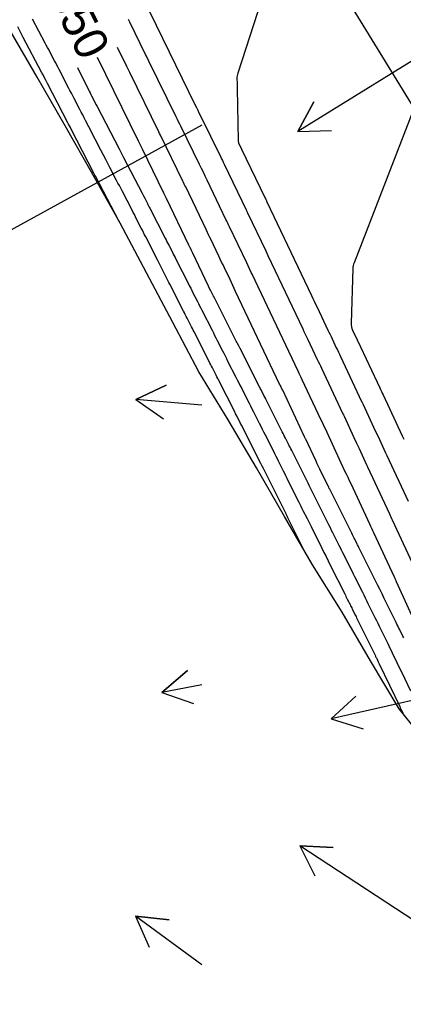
# Model space of a CAD drawing. Extents: x 954385 to 988206, y 1868364 to 1924553.
# Drawn here: x 956974.6 to 957043.1, y 1920910.1 to 1921087.7 of the extents above; entities that cross this region are included whole.
import ezdxf

# ---------------------------------------------------------------- set-up
doc = ezdxf.new("R2010")
doc.units = 0
for name, color, linetype in [('Default', 7, 'Continuous'), ('Ex_Contour Labels', 7, 'Continuous'), ('Ex_Major Contours', 7, 'Continuous'), ('Ex_Minor Contours', 7, 'Continuous'), ('Perimeter', 7, 'Continuous'), ('Slopes', 7, 'Continuous')]:
    doc.layers.add(name, color=color, linetype=linetype)

msp = doc.modelspace()

# ---------------------------------------------------------------- linework, layer by layer
at = {"layer": 'Default'}
msp.add_line((957221.14, 1920784.24), (956045.8, 1922705.18), dxfattribs=at)
at = {"layer": 'Ex_Major Contours'}
for points in [[(957044.52, 1920967.81), (957042.89, 1920971.21), (957042.69, 1920971.64), (957042.48, 1920972.06), (957042.28, 1920972.48), (957042.07, 1920972.91), (957041.26, 1920974.6), (957041.06, 1920975.03), (957040.85, 1920975.45), (957040.64, 1920975.87), (957040.44, 1920976.3), (957038.9, 1920979.4), (957038.66, 1920979.91), (957038.41, 1920980.41), (957038.16, 1920980.92), (957037.91, 1920981.42), (957036.91, 1920983.45), (957036.66, 1920983.95), (957036.41, 1920984.46), (957036.16, 1920984.96), (957035.91, 1920985.47), (957034.52, 1920988.22), (957034.26, 1920988.75), (957034, 1920989.27), (957033.74, 1920989.79), (957033.48, 1920990.31), (957032.36, 1920992.54), (957032.14, 1920992.99), (957031.92, 1920993.43), (957031.7, 1920993.87), (957031.47, 1920994.32), (957030.58, 1920996.09), (957030.36, 1920996.54), (957030.14, 1920996.98), (957029.92, 1920997.43), (957029.69, 1920997.87), (957027.79, 1921001.68), (957027.6, 1921002.04), (957027.42, 1921002.4), (957027.24, 1921002.77), (957027.06, 1921003.13), (957026.33, 1921004.58), (957026.15, 1921004.95), (957025.97, 1921005.31), (957025.78, 1921005.67), (957025.6, 1921006.04), (957023.21, 1921010.82), (957023.07, 1921011.1), (957022.93, 1921011.38), (957022.79, 1921011.65), (957022.65, 1921011.93), (957022.09, 1921013.04), (957021.95, 1921013.31), (957021.81, 1921013.59), (957021.67, 1921013.87), (957021.53, 1921014.14), (957018.6, 1921019.96), (957018.5, 1921020.15), (957018.41, 1921020.33), (957018.31, 1921020.52), (957018.22, 1921020.71), (957017.83, 1921021.46), (957017.74, 1921021.65), (957017.64, 1921021.84), (957017.55, 1921022.02), (957017.45, 1921022.21), (957013.97, 1921029.06), (957013.86, 1921029.27), (957013.75, 1921029.49), (957013.53, 1921029.92), (957013.42, 1921030.14), (957013.31, 1921030.35), (957009.33, 1921038.18), (957009.22, 1921038.39), (957008.69, 1921039.43), (957008.6, 1921039.61), (957008.51, 1921039.79), (957008.42, 1921039.97), (957008.34, 1921040.15), (957005.46, 1921046.18), (957005.31, 1921046.51), (957005.05, 1921047.05), (957005, 1921047.16), (957004.94, 1921047.27), (957004.89, 1921047.38), (957004.84, 1921047.48), (957000.82, 1921055.85), (957000.7, 1921056.09), (957000.59, 1921056.32), (957000.47, 1921056.56), (957000.36, 1921056.79), (956996.52, 1921064.63), (956996.34, 1921064.99), (956996.17, 1921065.34), (956995.99, 1921065.7), (956995.82, 1921066.05), (956988.48, 1921081.03)], [(957044.97, 1921071.73), (957034.36, 1921044.36), (957034.27, 1921044.1), (957034.21, 1921043.84), (957034.16, 1921043.57), (957034.14, 1921043.3), (957033.85, 1921033.57), (957033.85, 1921033.24), (957033.9, 1921032.92), (957033.99, 1921032.6), (957034.11, 1921032.29), (957034.92, 1921030.6), (957034.95, 1921030.54), (957034.98, 1921030.47), (957035.01, 1921030.41), (957035.04, 1921030.35), (957038.97, 1921022.02), (957039.12, 1921021.7), (957039.27, 1921021.38), (957039.42, 1921021.06), (957039.57, 1921020.74), (957042.97, 1921013.43), (957043.25, 1921012.84)]]:
    msp.add_lwpolyline(points, dxfattribs=at)
at = {"layer": 'Ex_Minor Contours'}
for points in [[(957022.06, 1921104.33), (957013.56, 1921078.19), (957013.5, 1921077.97), (957013.45, 1921077.75), (957013.43, 1921077.52), (957013.42, 1921077.29), (957013.44, 1921076.38), (957013.45, 1921076.15), (957013.45, 1921075.92), (957013.46, 1921075.69), (957013.46, 1921075.46), (957013.65, 1921066.16), (957013.66, 1921066.02), (957013.68, 1921065.88), (957013.72, 1921065.74), (957013.78, 1921065.61), (957014.22, 1921064.72), (957014.24, 1921064.68), (957014.26, 1921064.64), (957018.42, 1921055.98), (957018.5, 1921055.8), (957018.59, 1921055.62), (957018.68, 1921055.43), (957018.77, 1921055.25), (957026.75, 1921038.5), (957027, 1921037.98), (957027.24, 1921037.46), (957027.49, 1921036.94), (957027.74, 1921036.42), (957029.69, 1921032.33), (957029.88, 1921031.93), (957030.07, 1921031.54), (957030.25, 1921031.15), (957030.44, 1921030.75), (957031.19, 1921029.18), (957031.38, 1921028.78), (957031.57, 1921028.39), (957031.75, 1921027.99), (957031.94, 1921027.6), (957035.72, 1921019.58), (957035.79, 1921019.44), (957035.86, 1921019.29), (957035.93, 1921019.14), (957036, 1921019), (957037.86, 1921015), (957038.22, 1921014.21), (957038.59, 1921013.43), (957040, 1921010.39), (957040.06, 1921010.28), (957040.11, 1921010.17), (957040.16, 1921010.06), (957040.21, 1921009.94), (957044.02, 1921001.77)], [(957025.46, 1920992.97), (957022.54, 1920998.8), (957022.45, 1920998.99), (957022.28, 1920999.32), (957022.26, 1920999.37), (957018.38, 1921007.12), (957018.32, 1921007.23), (957018.26, 1921007.34), (957018.21, 1921007.46), (957018.15, 1921007.57), (957017.92, 1921008.02), (957017.87, 1921008.13), (957017.81, 1921008.25), (957017.75, 1921008.36), (957017.7, 1921008.47), (957014.23, 1921015.34), (957014.14, 1921015.53), (957014.04, 1921015.71), (957013.95, 1921015.9), (957013.85, 1921016.08), (957013.48, 1921016.83), (957013.38, 1921017.02), (957013.29, 1921017.2), (957013.19, 1921017.39), (957013.1, 1921017.58), (957010.12, 1921023.43), (957009.98, 1921023.7), (957009.84, 1921023.97), (957009.71, 1921024.24), (957009.57, 1921024.51), (957009.02, 1921025.6), (957008.88, 1921025.87), (957008.74, 1921026.14), (957008.6, 1921026.41), (957008.46, 1921026.69), (957005.77, 1921031.99), (957005.61, 1921032.3), (957005.45, 1921032.61), (957005.29, 1921032.92), (957005.14, 1921033.23), (957004.51, 1921034.47), (957004.35, 1921034.77), (957004.19, 1921035.08), (957004.03, 1921035.39), (957003.88, 1921035.7), (957001.43, 1921040.5), (957001.26, 1921040.85), (957001.08, 1921041.2), (957000.9, 1921041.56), (957000.72, 1921041.91), (957000, 1921043.32), (956999.82, 1921043.67), (956999.64, 1921044.02), (956999.46, 1921044.37), (956999.28, 1921044.73), (956997.12, 1921048.95), (956996.91, 1921049.35), (956996.71, 1921049.75), (956996.5, 1921050.15), (956996.3, 1921050.55), (956995.48, 1921052.15), (956995.28, 1921052.55), (956995.07, 1921052.95), (956994.86, 1921053.35), (956994.66, 1921053.75), (956992.87, 1921057.19), (956992.63, 1921057.65), (956992.39, 1921058.12), (956992.14, 1921058.58), (956991.9, 1921059.05), (956990.69, 1921061.38), (956989.97, 1921062.78), (956988.63, 1921065.34), (956988.35, 1921065.88), (956988.07, 1921066.42), (956987.79, 1921066.96), (956987.51, 1921067.5), (956986.33, 1921069.77), (956986.08, 1921070.26), (956985.83, 1921070.74), (956985.58, 1921071.23), (956985.32, 1921071.71), (956984.32, 1921073.66), (956984.06, 1921074.14), (956983.81, 1921074.63), (956983.56, 1921075.12), (956983.31, 1921075.6), (956981.62, 1921078.84), (956981.42, 1921079.24), (956981.21, 1921079.64), (956981, 1921080.03), (956980.79, 1921080.43), (956979.96, 1921082.01), (956979.75, 1921082.41), (956979.54, 1921082.8), (956979.33, 1921083.2), (956979.12, 1921083.59), (956976.85, 1921087.88)], [(957045.96, 1920978.61), (957041.98, 1920987.34), (957041.89, 1920987.54), (957041.79, 1920987.75), (957041.7, 1920987.95), (957041.6, 1920988.16), (957037.91, 1920996.09), (957037.72, 1920996.48), (957037.54, 1920996.87), (957037.36, 1920997.26), (957037.17, 1920997.66), (957033.83, 1921004.83), (957033.56, 1921005.41), (957033.29, 1921005.99), (957033.01, 1921006.57), (957032.74, 1921007.15), (957029.56, 1921014), (957029.3, 1921014.55), (957029.03, 1921015.11), (957028.77, 1921015.67), (957028.51, 1921016.23), (957025.1, 1921023.46), (957024.92, 1921023.84), (957024.74, 1921024.21), (957024.57, 1921024.59), (957024.39, 1921024.96), (957016.12, 1921042.32), (957015.98, 1921042.6), (957015.42, 1921043.78), (957015.17, 1921044.31), (957012.08, 1921050.79), (957011.93, 1921051.11), (957011.77, 1921051.44), (957011.61, 1921051.77), (957011.45, 1921052.1), (957008.08, 1921059.12), (957007.75, 1921059.81), (957007.41, 1921060.5), (957007.07, 1921061.19), (957006.74, 1921061.88), (957003.42, 1921068.64), (957003.21, 1921069.08), (957002.99, 1921069.52), (957002.78, 1921069.96), (957002.56, 1921070.39), (956997.68, 1921080.36), (956997.23, 1921081.27), (956997.08, 1921081.57), (956994.26, 1921087.33), (956994.2, 1921087.44), (956994.15, 1921087.56), (956994.09, 1921087.67), (956994.04, 1921087.78)], [(956997.77, 1921089.21), (957005.96, 1921072.52), (957006.18, 1921072.06), (957006.4, 1921071.61), (957006.63, 1921071.15), (957006.85, 1921070.69), (957010.53, 1921063.19), (957010.68, 1921062.89), (957010.82, 1921062.59), (957010.97, 1921062.29), (957011.12, 1921061.98), (957015.05, 1921053.81), (957015.11, 1921053.67), (957015.18, 1921053.53), (957015.25, 1921053.39), (957015.31, 1921053.25), (957018.56, 1921046.45), (957018.94, 1921045.65), (957025.18, 1921032.54), (957025.41, 1921032.06), (957025.64, 1921031.59), (957025.86, 1921031.11), (957026.09, 1921030.64), (957027.79, 1921027.07), (957027.97, 1921026.68), (957028.16, 1921026.3), (957028.34, 1921025.92), (957028.52, 1921025.53), (957032.32, 1921017.48), (957032.38, 1921017.34), (957032.45, 1921017.2), (957032.51, 1921017.06), (957032.58, 1921016.92), (957034.35, 1921013.11), (957034.81, 1921012.13), (957035.27, 1921011.14), (957036.62, 1921008.25), (957036.66, 1921008.16), (957036.7, 1921008.08), (957036.74, 1921008), (957036.78, 1921007.91), (957040.7, 1920999.5), (957040.82, 1920999.23), (957040.95, 1920998.96), (957041.08, 1920998.69), (957041.2, 1920998.42), (957044.77, 1920990.77)], [(956992.34, 1921051.71), (956988.12, 1921059.84), (956988.03, 1921060.02), (956987.85, 1921060.37), (956983.78, 1921068.19), (956983.63, 1921068.48), (956983.32, 1921069.08), (956983.17, 1921069.37), (956979.53, 1921076.39), (956979.35, 1921076.72), (956979.18, 1921077.06), (956978.83, 1921077.74), (956978.74, 1921077.9), (956978.65, 1921078.07), (956978.56, 1921078.24), (956978.47, 1921078.41), (956975.21, 1921084.58), (956974.96, 1921085.05), (956974.71, 1921085.52), (956974.22, 1921086.46)], [(957043.26, 1920977.33), (957043.11, 1920977.64), (957042.5, 1920978.87), (957042.34, 1920979.18), (957042.19, 1920979.49), (957042.04, 1920979.8), (957041.89, 1920980.11), (957039.78, 1920984.39), (957039.37, 1920985.21), (957038.97, 1920986.02), (957038.56, 1920986.84), (957038.16, 1920987.65), (957035.23, 1920993.49), (957035.16, 1920993.64), (957035.08, 1920993.79), (957035.01, 1920993.94), (957034.93, 1920994.09), (957034.61, 1920994.74), (957034.54, 1920994.87), (957034.48, 1920995), (957034.41, 1920995.13), (957034.35, 1920995.25), (957034.09, 1920995.77), (957033.96, 1920996.03), (957033.83, 1920996.29), (957030.02, 1921003.89), (957029.94, 1921004.05), (957029.84, 1921004.25), (957029.78, 1921004.38), (957028.45, 1921007.04), (957028.22, 1921007.5), (957027.99, 1921007.95), (957027.77, 1921008.42), (957027.56, 1921008.88), (957025.72, 1921012.82), (957025.67, 1921012.92), (957025.62, 1921013.03), (957025.57, 1921013.13), (957025.53, 1921013.23), (957021.6, 1921021.56), (957021.46, 1921021.84), (957021.33, 1921022.12), (957021.2, 1921022.41), (957021.06, 1921022.69), (957013.18, 1921039.23), (957012.93, 1921039.75), (957012.68, 1921040.28), (957012.43, 1921040.8), (957012.18, 1921041.33), (957011.18, 1921043.43), (957010.93, 1921043.95), (957010.68, 1921044.48), (957010.43, 1921045), (957010.18, 1921045.52), (957008.73, 1921048.57), (957008.54, 1921048.96), (957008.36, 1921049.35), (957008.17, 1921049.75), (957007.98, 1921050.14), (957004.26, 1921057.88), (957004.13, 1921058.14), (957004, 1921058.41), (957003.87, 1921058.68), (957003.74, 1921058.95), (956999.73, 1921067.13), (956999.58, 1921067.43), (956999.43, 1921067.73), (956994.24, 1921078.34), (956993.84, 1921079.15), (956993.7, 1921079.42), (956992.04, 1921082.81)], [(956984.92, 1921079.24), (956986.88, 1921075.25), (956987.01, 1921074.98), (956987.15, 1921074.7), (956987.29, 1921074.43), (956987.43, 1921074.16), (956988.25, 1921072.57), (956988.42, 1921072.25), (956992.33, 1921064.72), (956992.46, 1921064.46), (956992.6, 1921064.2), (956993.15, 1921063.15), (956996.47, 1921056.76), (956996.7, 1921056.31), (956996.93, 1921055.86), (956997.4, 1921054.96), (956997.51, 1921054.74), (956997.63, 1921054.51), (956997.75, 1921054.29), (956997.86, 1921054.07), (957000.59, 1921048.74), (957000.75, 1921048.42), (957000.91, 1921048.11), (957001.07, 1921047.79), (957001.23, 1921047.48), (957001.88, 1921046.22), (957002.04, 1921045.9), (957002.2, 1921045.59), (957002.36, 1921045.27), (957002.52, 1921044.96), (957004.76, 1921040.56), (957004.96, 1921040.17), (957005.16, 1921039.78), (957005.36, 1921039.39), (957005.56, 1921039), (957006.35, 1921037.43), (957006.55, 1921037.04), (957006.75, 1921036.65), (957006.95, 1921036.26), (957007.15, 1921035.87), (957008.97, 1921032.29), (957009.2, 1921031.83), (957009.43, 1921031.37), (957009.67, 1921030.92), (957009.9, 1921030.46), (957010.83, 1921028.63), (957011.07, 1921028.17), (957011.3, 1921027.71), (957011.53, 1921027.25), (957011.76, 1921026.79), (957013.22, 1921023.94), (957013.48, 1921023.42), (957013.74, 1921022.9), (957014.01, 1921022.39), (957014.27, 1921021.87), (957015.32, 1921019.8), (957015.59, 1921019.28), (957015.85, 1921018.77), (957016.11, 1921018.25), (957016.37, 1921017.74), (957017.41, 1921015.68), (957017.67, 1921015.17), (957017.93, 1921014.65), (957018.19, 1921014.14), (957018.45, 1921013.62), (957019.93, 1921010.68), (957020.15, 1921010.25), (957020.37, 1921009.81), (957020.59, 1921009.38), (957020.81, 1921008.94), (957021.68, 1921007.2), (957021.9, 1921006.76), (957022.11, 1921006.33), (957022.33, 1921005.89), (957022.55, 1921005.46), (957024.5, 1921001.56), (957024.68, 1921001.2), (957024.86, 1921000.84), (957025.05, 1921000.48), (957025.23, 1921000.11), (957025.95, 1920998.66), (957026.14, 1920998.3), (957026.32, 1920997.94), (957026.5, 1920997.58), (957026.68, 1920997.21), (957028.6, 1920993.38), (957028.98, 1920992.62), (957029.36, 1920991.87), (957029.74, 1920991.11), (957030.12, 1920990.35), (957032.69, 1920985.21), (957032.81, 1920984.98), (957032.92, 1920984.74), (957033.04, 1920984.51), (957033.16, 1920984.28), (957033.66, 1920983.28), (957033.75, 1920983.09), (957033.85, 1920982.89), (957033.95, 1920982.7), (957034.04, 1920982.5), (957034.43, 1920981.72), (957034.52, 1920981.53), (957034.62, 1920981.33), (957034.72, 1920981.14), (957034.81, 1920980.94), (957038.18, 1920974.13), (957038.23, 1920974.01), (957038.29, 1920973.89), (957038.35, 1920973.77), (957038.41, 1920973.64), (957038.7, 1920973.04), (957038.87, 1920972.68), (957042.53, 1920965.07), (957042.64, 1920964.82), (957042.76, 1920964.58), (957043.12, 1920963.83)]]:
    msp.add_lwpolyline(points, dxfattribs=at)
at = {"layer": 'Perimeter'}
msp.add_lwpolyline([(957098.4, 1920905.15), (957092.36, 1920913.18), (957085.57, 1920920.75), (957080.38, 1920929.3), (957070.14, 1920934.75), (957061.48, 1920941.18), (957054.9, 1920948.88), (957048.74, 1920956.83), (957042.43, 1920964.69), (957037.28, 1920973.26), (957032.25, 1920981.91), (957026.96, 1920990.4), (957021.92, 1920999.04), (957016.92, 1921007.7), (957011.84, 1921016.31), (957006.63, 1921024.85), (957001.93, 1921033.7), (956997.23, 1921042.55), (956992.52, 1921051.39), (956987.62, 1921060.12), (956982.7, 1921068.82), (956977.71, 1921077.5), (956972.71, 1921086.16), (956967.65, 1921094.79)], dxfattribs=at)
at = {"layer": 'Slopes'}
for points in [[(957107.13, 1921118.93), (957024.32, 1921067.81), (957027.16, 1921073.09), (957024.32, 1921067.81), (957030.32, 1921067.99)], [(957007.13, 1921068.93), (956892.31, 1921005.94), (956895.42, 1921011.07), (956892.31, 1921005.94), (956898.31, 1921005.81)], [(957007.13, 1921018.93), (956995.34, 1921019.9), (957000.77, 1921022.46), (956995.34, 1921019.9), (957000.28, 1921016.48)], [(957007.13, 1920968.93), (957000, 1920967.61), (957004.57, 1920971.51), (957000, 1920967.61), (957005.66, 1920965.61)], [(957057.13, 1920968.93), (957030.29, 1920962.87), (957034.7, 1920966.94), (957030.29, 1920962.87), (957036.02, 1920961.09)], [(957057.13, 1920918.93), (957024.64, 1920940.21), (957030.63, 1920939.87), (957024.64, 1920940.21), (957027.35, 1920934.86)], [(957007.13, 1920918.93), (956995.3, 1920927.61), (957001.27, 1920926.96), (956995.3, 1920927.61), (956997.72, 1920922.12)]]:
    msp.add_lwpolyline(points, dxfattribs=at)

# ---------------------------------------------------------------- texts
at = {"layer": 'Ex_Contour Labels'}
msp.add_text('550', height=6, rotation=296.634, dxfattribs=at).set_placement((956979.55, 1921092.13))

doc.saveas('drawing.dxf')
